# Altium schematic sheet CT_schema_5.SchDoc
size 422 x 246 mm
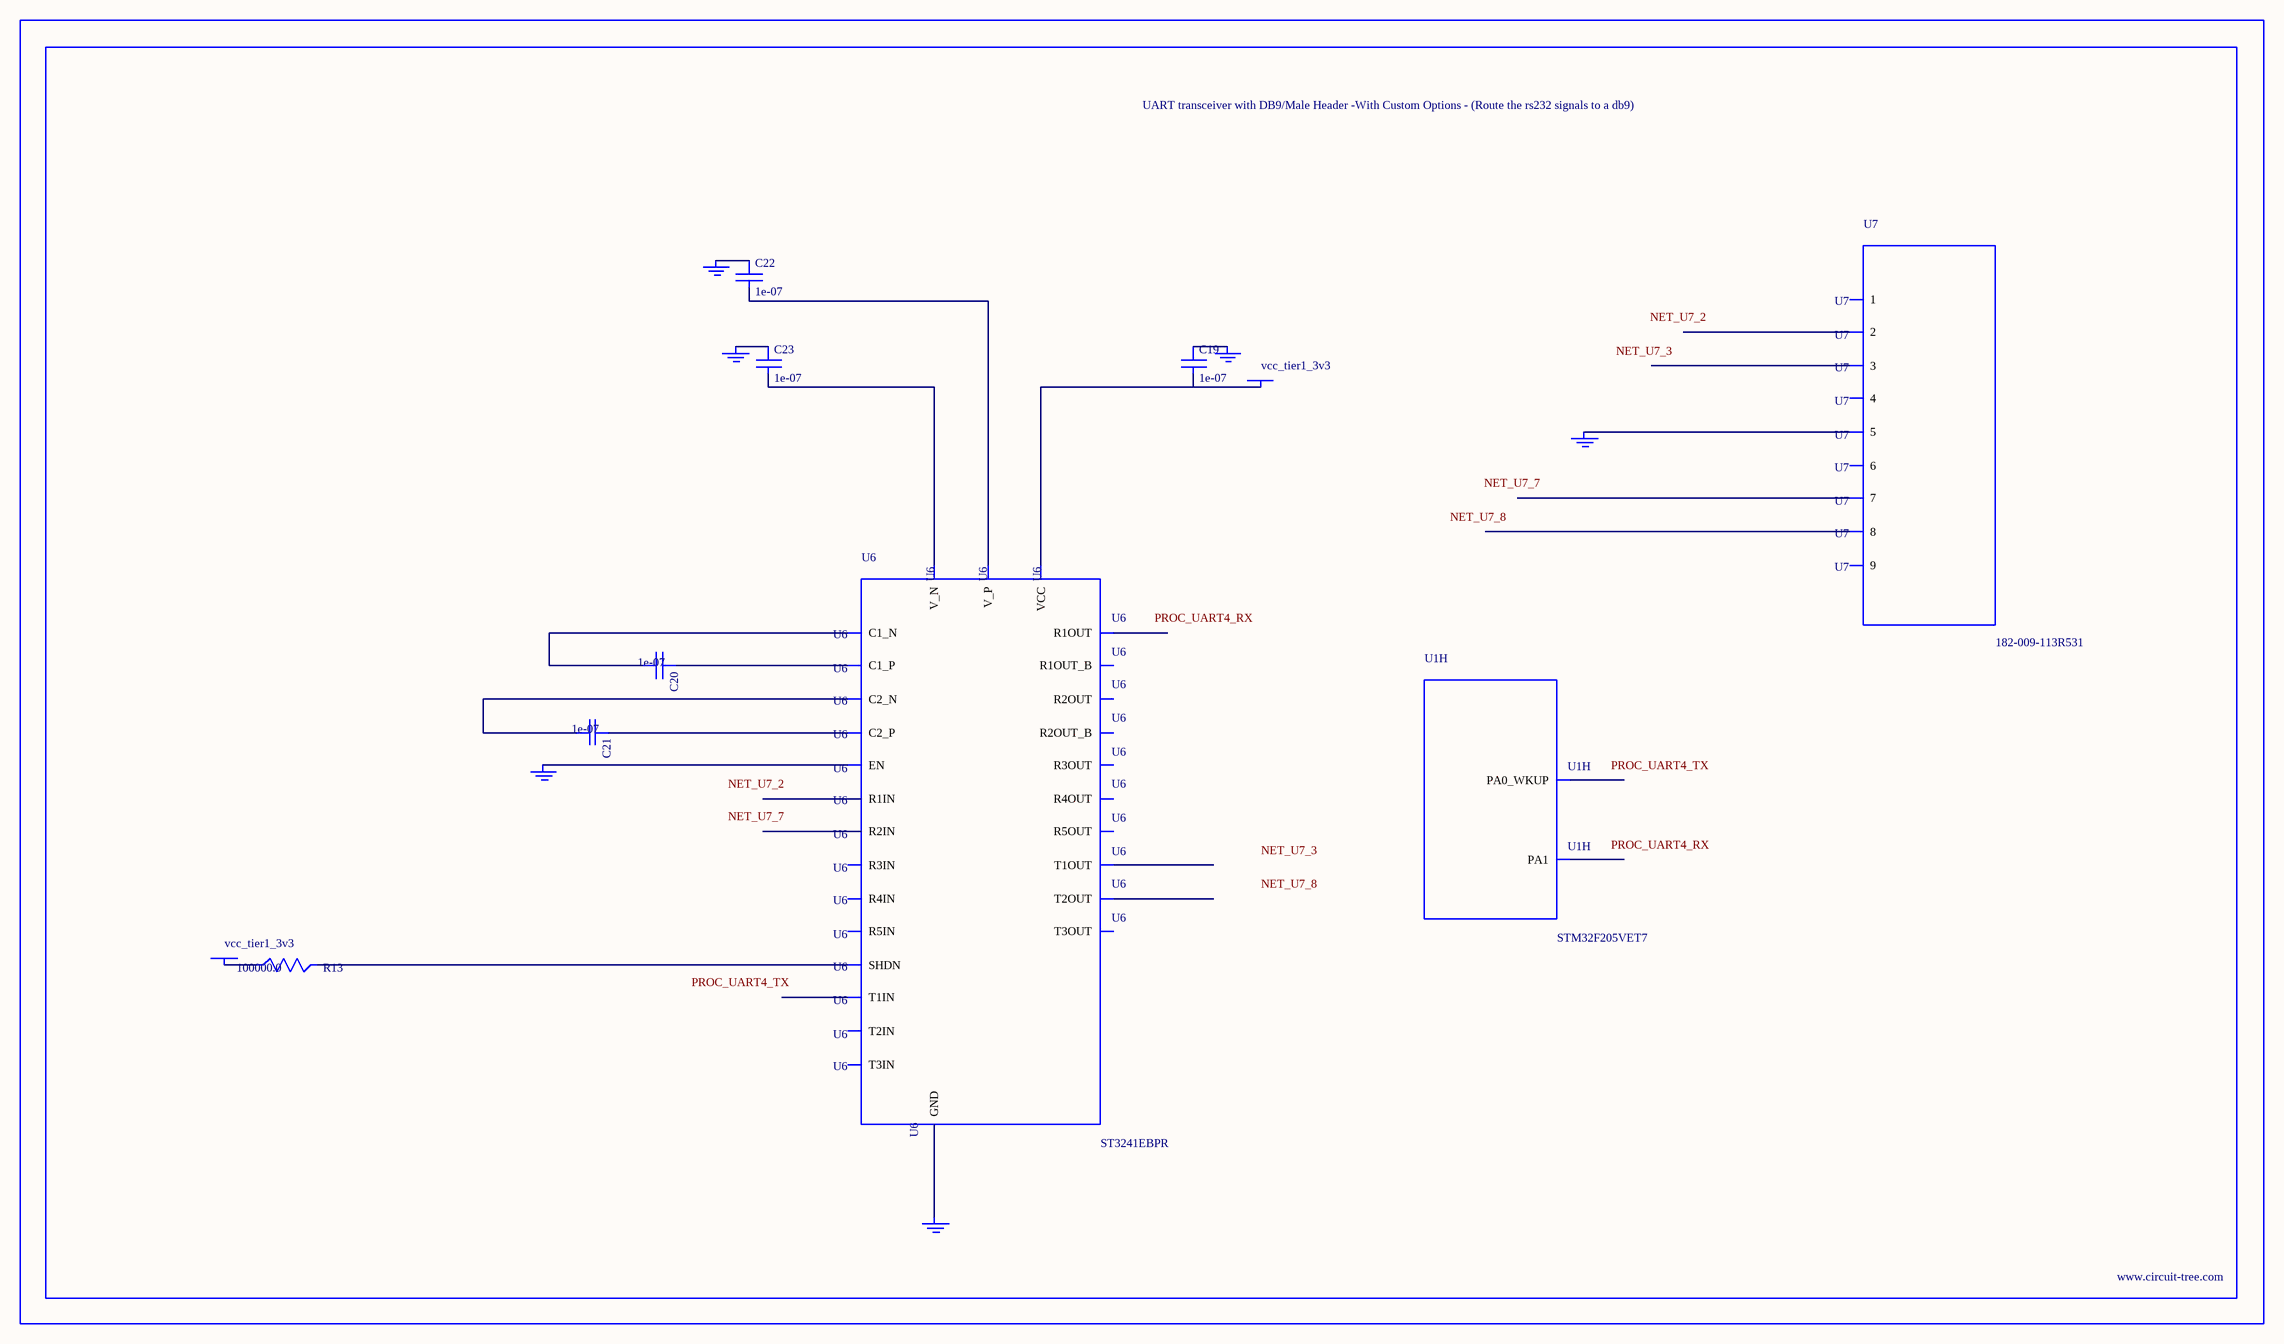
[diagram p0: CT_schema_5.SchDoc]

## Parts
BORDER4  (no value)
C19  1e-07  [C0402]
C20  1e-07  [C0402]
C21  1e-07  [C0402]
C22  1e-07  [C0402]
C23  1e-07  [C0402]
GND_INSTANCE_4_0  (no value)
GND_INSTANCE_4_1  (no value)
GND_INSTANCE_4_2  (no value)
GND_INSTANCE_4_3  (no value)
GND_INSTANCE_4_4  (no value)
GND_INSTANCE_4_5  (no value)
POWER_INSTANCE_4_0  vcc_tier1_3v3
POWER_INSTANCE_4_1  vcc_tier1_3v3
R13  100000.0  [R0603]
U1  STM32F205VET7  [LQFP100]  (part H of 11)
U6  ST3241EBPR  [SSOP-28]
U7  182-009-113R531  [182-009-MALE]

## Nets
NetC19_1: C19.1 GND_INSTANCE_4_2.0(GND)
NetC19_2: C19.2 POWER_INSTANCE_4_1.0(PWR) U6.26(VCC)
NetC20_1: C20.1 U6.28(C1_P)
NetC20_2: C20.2 U6.24(C1_N)
NetC21_1: C21.1 U6.1(C2_P)
NetC21_2: C21.2 U6.2(C2_N)
NetC22_1: C22.1 GND_INSTANCE_4_3.0(GND)
NetC22_2: C22.2 U6.27(V_P)
NetC23_1: C23.1 GND_INSTANCE_4_0.0(GND)
NetC23_2: C23.2 U6.3(V_N)
NetGND_INSTANCE_4_1_0: GND_INSTANCE_4_1.0(GND) U6.23(EN)
NetGND_INSTANCE_4_4_0: GND_INSTANCE_4_4.0(GND) U6.25(GND)
NetGND_INSTANCE_4_5_0: GND_INSTANCE_4_5.0(GND) U7.5
NetPOWER_INSTANCE_4_0_0: POWER_INSTANCE_4_0.0(PWR) R13.1
NetR13_2: R13.2 U6.22(SHDN)

Not connected (* = marked no-connect by the designer): U1 23(PA0_WKUP) 24(PA1); U6 4(R1IN) 5(R2IN) 6(R3IN) 7(R4IN) 8(R5IN) 9(T1OUT) 10(T2OUT) 11(T3OUT) 12(T3IN) 13(T2IN) 14(T1IN) 15(R5OUT) 16(R4OUT) 17(R3OUT) 18(R2OUT) 19(R1OUT) 20(R2OUT_B) 21(R1OUT_B); U7 1 2 3 4 6 7 8 9

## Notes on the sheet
- Labels drawn without touching a wire or pin: NET_U7_2, NET_U7_3, NET_U7_7, NET_U7_8, PROC_UART4_RX, PROC_UART4_TX

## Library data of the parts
BORDER4 = BORDER_PAGE4
C19-C23 = C0402C104K3RACTU
GND_INSTANCE_4_0-GND_INSTANCE_4_5 = GND
POWER_INSTANCE_4_0 POWER_INSTANCE_4_1 = PWR
R13 = RC0603JR-07100KL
